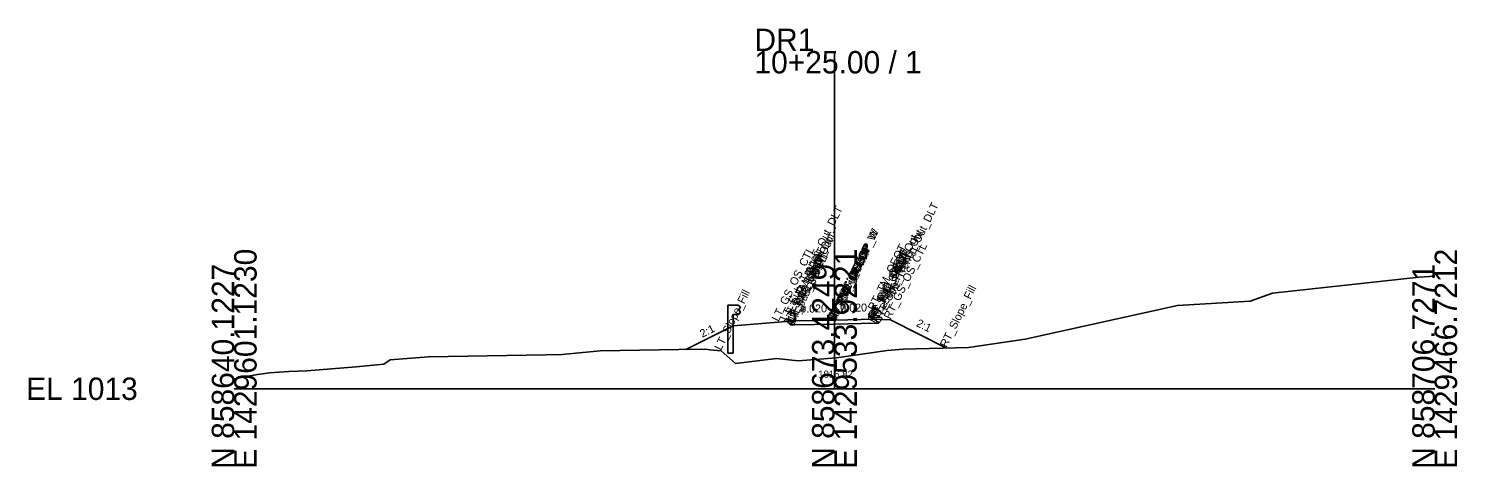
# Model space of a CAD drawing. Extents: x -26 to 1303, y -10 to 1029.
# Drawn here: x 1124.3 to 1302.8, y -9.7 to 45 of the extents above; entities that cross this region are included whole.
import ezdxf

# ---------------------------------------------------------------- set-up
doc = ezdxf.new("R2010")
doc.units = 0
for name, color, linetype in [('Default', 7, 'Continuous'), ('Exist Cross Section Cell', 7, 'Continuous'), ('Exist XS Center Line Elevation Label', 7, 'Continuous'), ('Exist XS Ground Line', 7, 'Continuous'), ('Prop CMT Guardrail Graphics', 7, 'Continuous'), ('Prop CMT Pvmt Course 1', 7, 'Continuous'), ('Prop CMT Pvmt Course 2', 7, 'Continuous'), ('Prop CMT Pvmt Surface', 7, 'Continuous'), ('Prop CMT Pvmt Surface Overlay', 7, 'Continuous'), ('Prop CMT Shld Paved Course 1', 7, 'Continuous'), ('Prop CMT Shld Paved Course 2', 7, 'Continuous'), ('Prop CMT Slope Grass', 7, 'Continuous'), ('Prop CMT Subgrade Earthwork', 7, 'Continuous'), ('Prop XS Dump Level', 7, 'Continuous'), ('Prop XS EOT Tick Mark', 7, 'Continuous'), ('Prop XS SE Text', 7, 'Continuous'), ('Prop XS Side Slope Text', 7, 'Continuous')]:
    doc.layers.add(name, color=color, linetype=linetype)

msp = doc.modelspace()

# ---------------------------------------------------------------- linework, layer by layer
at = {"layer": 'Exist Cross Section Cell'}
for p, q in [((1225, 0), (1225, 42.16)), ((1150, 0), (1225, 0)), ((1225, 0), (1300, 0))]:
    msp.add_line(p, q, dxfattribs=at)
at = {"layer": 'Exist XS Ground Line'}
msp.add_lwpolyline([(1150, 1.23), (1152.9, 1.79), (1154.41, 1.99), (1156.82, 2.14), (1159.09, 2.23), (1165.25, 2.75), (1168.69, 3.06), (1169.48, 3.63), (1174.28, 4), (1188.98, 4.23), (1190.98, 4.27), (1195.71, 4.73), (1205.54, 4.9), (1208.88, 4.94), (1209.41, 4.86), (1210.83, 4.72), (1212.65, 3.15), (1217.76, 3.76), (1220.46, 3.48), (1225.24, 3.84), (1231.57, 4.77), (1233.6, 4.96), (1241.75, 5.16), (1248.84, 6.18), (1267.85, 10.4), (1276.93, 10.95), (1279.72, 11.95), (1298.06, 13.92), (1300, 14.05)], dxfattribs=at)
at = {"layer": 'Prop CMT Guardrail Graphics'}
for points in [[(1211.66, 4.44), (1211.66, 10.44)], [(1211.66, 10.44), (1213, 10.44), (1213.27, 10.15)], [(1213.27, 9.56), (1213, 9.27), (1212.33, 9.27)], [(1212.33, 9.27), (1212.33, 4.44)], [(1213.27, 10.15), (1213, 9.85)], [(1213, 9.85), (1213.27, 9.56)], [(1212.33, 4.44), (1211.66, 4.44)]]:
    msp.add_lwpolyline(points, dxfattribs=at)
at = {"layer": 'Prop CMT Pvmt Course 1'}
for points in [[(1225, 8.57), (1220, 8.47)], [(1225, 8.57), (1230, 8.67)]]:
    msp.add_lwpolyline(points, dxfattribs=at)
at = {"layer": 'Prop CMT Pvmt Course 2'}
for points in [[(1220, 7.97), (1225, 8.07)], [(1230, 8.17), (1225, 8.07)]]:
    msp.add_lwpolyline(points, dxfattribs=at)
at = {"layer": 'Prop CMT Pvmt Surface'}
for points in [[(1225, 8.57), (1220, 8.47)], [(1225, 8.57), (1230, 8.67)]]:
    msp.add_lwpolyline(points, dxfattribs=at)
at = {"layer": 'Prop CMT Pvmt Surface Overlay'}
for points in [[(1225, 8.57), (1220, 8.47)], [(1225, 8.57), (1230, 8.67)]]:
    msp.add_lwpolyline(points, dxfattribs=at)
at = {"layer": 'Prop CMT Shld Paved Course 1'}
for points in [[(1220, 8.47), (1219.74, 8.21)], [(1230, 8.67), (1230.25, 8.42)]]:
    msp.add_lwpolyline(points, dxfattribs=at)
at = {"layer": 'Prop CMT Shld Paved Course 2'}
for points in [[(1219.74, 8.21), (1219.49, 7.96)], [(1219.49, 7.96), (1220, 7.97)], [(1219.74, 8.21), (1219.74, 8.21)], [(1230.49, 8.18), (1230, 8.17)], [(1230.25, 8.42), (1230.25, 8.42)], [(1230.25, 8.42), (1230.49, 8.18)]]:
    msp.add_lwpolyline(points, dxfattribs=at)
at = {"layer": 'Prop CMT Slope Grass'}
for points in [[(1220, 8.48), (1212.35, 7.86), (1206.43, 4.91)], [(1230, 8.67), (1232, 8.59), (1239.02, 5.08)]]:
    msp.add_lwpolyline(points, dxfattribs=at)
at = {"layer": 'Prop CMT Subgrade Earthwork'}
for points in [[(1225, 8.07), (1220, 7.97), (1219.49, 7.96), (1219.06, 8.39)], [(1225, 8.07), (1230, 8.17), (1230.49, 8.18), (1230.94, 8.63)]]:
    msp.add_lwpolyline(points, dxfattribs=at)
at = {"layer": 'Prop XS EOT Tick Mark'}
for points in [[(1220, 8.47), (1220, 9.47)], [(1230, 8.67), (1230, 9.67)]]:
    msp.add_lwpolyline(points, dxfattribs=at)

# ---------------------------------------------------------------- texts
at = {"layer": 'Default'}
msp.add_text('-', height=0.0001, dxfattribs=at).set_placement((1150, 0))
at = {"layer": 'Exist Cross Section Cell'}
for s, p in [('DR1', (1215, 42.16)), ('10+25.00 / 1', (1215, 39.36)), ('EL 1013', (1124, -1.4))]:
    msp.add_text(s, height=2.8, dxfattribs=at).set_placement(p)
for s, p in [('E 1429601.1230', (1152.8, -10)), ('E 1429533.9221', (1227.8, -10)), ('E 1429466.7212', (1302.8, -10)), ('N 858640.1227', (1150, -10)), ('N 858673.4249', (1225, -10)), ('N 858706.7271', (1300, -10))]:
    msp.add_text(s, height=2.8, rotation=90, dxfattribs=at).set_placement(p)
at = {"layer": 'Exist XS Center Line Elevation Label'}
msp.add_text('1016.82', height=0.9, dxfattribs=at).set_placement((1222.96, 1.37))
at = {"layer": 'Prop XS Dump Level'}
for s, p in [('RT_Sub_Trench_Out_DLT', (1230.94, 8.63)), ('LT_Sub_Trench_Out_DLT', (1219.06, 8.39)), ('RT_PV1_OEEOP_W', (1225, 8.44)), ('LT_PV1_OEEOP_W', (1225, 8.44)), ('RT_Sub_Trench_Out', (1230.49, 8.18)), ('LT_Sub_Trench_Out', (1219.49, 7.96)), ('LT_PS2_Shelf_Out', (1219.74, 8.21)), ('RT_PV2_OEEOP', (1225, 8.32)), ('LT_PV2_OEEOP', (1225, 8.32)), ('RT_TM_OEOT', (1230, 9.67)), ('RT_PS2_Shelf_Out', (1230.25, 8.42)), ('RT_GS_OS_CTL', (1232, 8.59)), ('LT_GS_OS_CTL', (1218, 8.31)), ('LT_PS2_OEOP', (1219.74, 8.21)), ('LT_TM_OEOT', (1220, 9.47)), ('LT_PV1_OEOT', (1220, 8.47)), ('LT_PV2_OEOT', (1220, 8.22)), ('LT_Sub_OEOT', (1220, 7.97)), ('RT_Sub_OEEOP', (1225, 8.07)), ('LT_Sub_OEEOP', (1225, 8.07)), ('RT_PV1_OEOT', (1230, 8.67)), ('RT_PV2_OEOT', (1230, 8.42)), ('RT_Sub_OEOT', (1230, 8.17)), ('RT_PS2_OEOP', (1230.25, 8.42)), ('PV1_PGL_W', (1225, 8.44)), ('PV1_PGL', (1225, 8.57)), ('RT_Slope_Fill', (1239.02, 5.08)), ('LT_Slope_Fill', (1210.83, 4.72))]:
    msp.add_text(s, height=1, rotation=63.5833, dxfattribs=at).set_placement(p)
at = {"layer": 'Prop XS SE Text'}
for p in [(1220.73, 9.48), (1225.73, 9.58)]:
    msp.add_text('0.020', height=1, rotation=1.1458, dxfattribs=at).set_placement(p)
at = {"layer": 'Prop XS Side Slope Text'}
for rotation, p in [(26.5651, (1208.49, 6.35)), (333.4349, (1235.14, 7.86))]:
    msp.add_text('2:1', height=1, rotation=rotation, dxfattribs=at).set_placement(p)

doc.saveas('drawing.dxf')
